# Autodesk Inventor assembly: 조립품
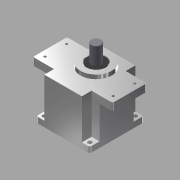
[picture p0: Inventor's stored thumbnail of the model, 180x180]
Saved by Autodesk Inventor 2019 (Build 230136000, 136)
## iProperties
Created: 2020-01
Part Number: 조립품
Material: 일반
Document SubType Name: Assembly
Designer: 323-19
Author: 323-19
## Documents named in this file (10)
- C:\Users\323-19\Desktop\700119V1004\조립품.iam
- C:\Users\323-19\Desktop\700119V1004\본체.ipt
- C:\Users\323-19\Desktop\700119V1004\서브 축.ipt
- C:\Users\323-19\Desktop\700119V1004\메인 축.ipt
- C:\Users\323-19\Desktop\700119V1004\베어링 608.ipt
- C:\Users\323-19\Desktop\700119V1004\베어링 6003.ipt
- C:\Users\323-19\Desktop\700119V1004\커버.ipt
- C:\Users\323-19\Desktop\700119V1004\오일 실 8 22 7.ipt
- C:\Users\323-19\Desktop\700119V1004\오일 실 17 32 8.ipt
- C:\Users\323-19\Desktop\700119V1004\볼트 M4.ipt
